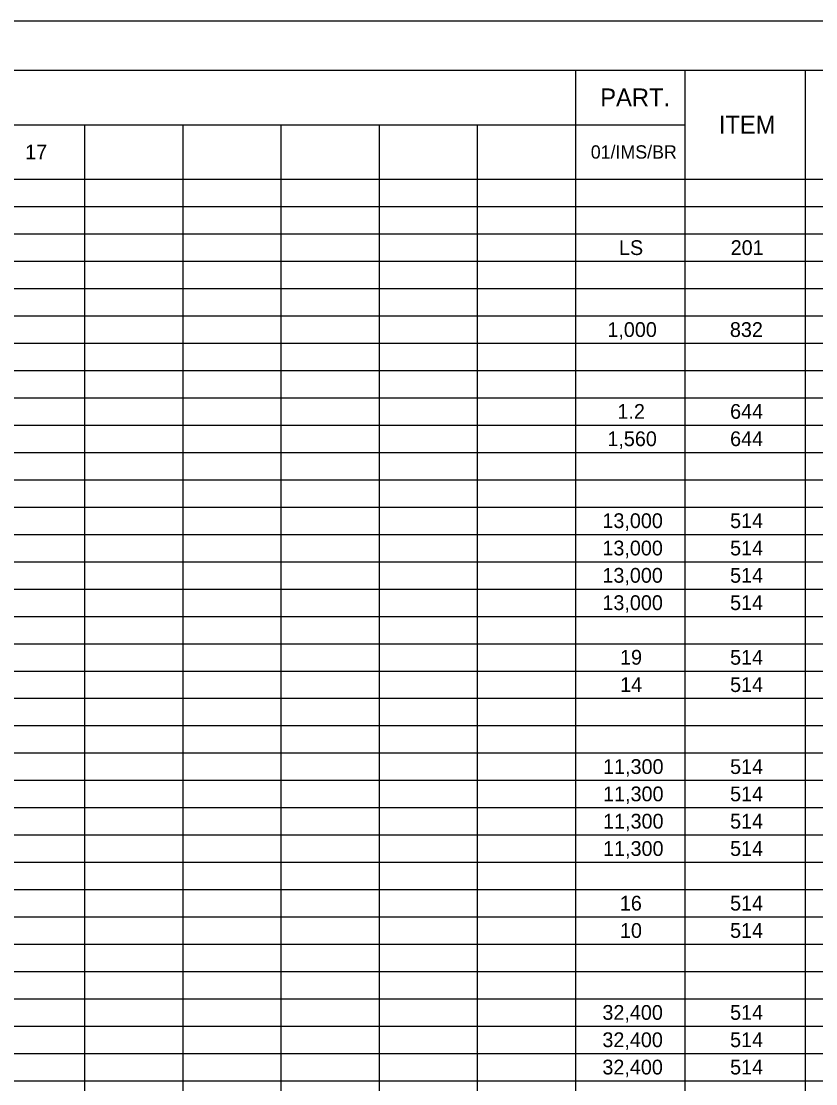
# Model space of a CAD drawing. Extents: x 0 to 34, y 0 to 22.
# Drawn here: x 8.9 to 17.04, y 11.11 to 22 of the extents above; entities that cross this region are included whole.
import ezdxf

# ---------------------------------------------------------------- set-up
doc = ezdxf.new("R2010")
doc.units = 0
for name, color, linetype in [('SH_Border', 7, 'Continuous'), ('SH_Cut_Line', 7, 'Continuous'), ('SH_Text', 7, 'Continuous')]:
    doc.layers.add(name, color=color, linetype=linetype)

msp = doc.modelspace()

# ---------------------------------------------------------------- linework, layer by layer
at = {"layer": 'SH_Border'}
msp.add_lwpolyline([(1.5, 21.5), (33.5, 21.5), (33.5, 0.5), (1.5, 0.5)], close=True, dxfattribs=at)
at = {"layer": 'SH_Cut_Line'}
msp.add_lwpolyline([(0, 0), (34, 0), (34, 22), (0, 22)], close=True, dxfattribs=at)
at = {"layer": 'SH_Text'}
for p, q in [((1.5, 21.5), (32, 21.5)), ((14.58, 21.5), (14.58, 0.502)), ((15.701, 21.5), (15.701, 0.502)), ((16.937, 21.5), (16.937, 0.502)), ((1.5, 20.94), (15.701, 20.94)), ((9.549, 20.94), (9.549, 0.502)), ((10.555, 20.94), (10.555, 0.502)), ((11.561, 20.94), (11.561, 0.502)), ((12.567, 20.94), (12.567, 0.502)), ((13.574, 20.94), (13.574, 0.502)), ((1.5, 20.38), (32, 20.38)), ((1.5, 20.1), (32, 20.1)), ((1.5, 19.82), (32, 19.82)), ((1.5, 19.54), (32, 19.54)), ((1.5, 19.26), (32, 19.26)), ((1.5, 18.98), (32, 18.98)), ((1.5, 18.7), (32, 18.7)), ((1.5, 18.42), (32, 18.42)), ((1.5, 18.14), (32, 18.14)), ((1.5, 17.86), (32, 17.86)), ((1.5, 17.58), (32, 17.58)), ((1.5, 17.3), (32, 17.3)), ((1.5, 17.02), (32, 17.02)), ((1.5, 16.74), (32, 16.74)), ((1.5, 16.46), (32, 16.46)), ((1.5, 16.18), (32, 16.18)), ((1.5, 15.9), (32, 15.9)), ((1.5, 15.62), (32, 15.62)), ((1.5, 15.34), (32, 15.34)), ((1.5, 15.061), (32, 15.061)), ((1.5, 14.781), (32, 14.781)), ((1.5, 14.501), (32, 14.501)), ((1.5, 14.221), (32, 14.221)), ((1.5, 13.941), (32, 13.941)), ((1.5, 13.661), (32, 13.661)), ((1.5, 13.381), (32, 13.381)), ((1.5, 13.101), (32, 13.101)), ((1.5, 12.821), (32, 12.821)), ((1.5, 12.541), (32, 12.541)), ((1.5, 12.261), (32, 12.261)), ((1.5, 11.981), (32, 11.981)), ((1.5, 11.701), (32, 11.701)), ((1.5, 11.421), (32, 11.421)), ((1.5, 11.141), (32, 11.141))]:
    msp.add_line(p, q, dxfattribs=at)

# ---------------------------------------------------------------- texts
for s, height, p in [('PART.', 0.1818, (14.835, 21.129)), ('ITEM', 0.1818, (16.05, 20.849)), ('17', 0.1515, (8.94, 20.584)), ('01/IMS/BR', 0.1364, (14.738, 20.592)), ('LS', 0.1515, (15.027, 19.604)), ('201', 0.1515, (16.172, 19.604)), ('1,000', 0.1515, (14.908, 18.764)), ('832', 0.1515, (16.164, 18.764)), ('1.2', 0.1515, (15.011, 17.925)), ('644', 0.1515, (16.166, 17.925)), ('1,560', 0.1515, (14.908, 17.645)), ('644', 0.1515, (16.166, 17.645)), ('13,000', 0.1515, (14.857, 16.805)), ('514', 0.1515, (16.166, 16.805)), ('13,000', 0.1515, (14.857, 16.525)), ('514', 0.1515, (16.166, 16.525)), ('13,000', 0.1515, (14.857, 16.245)), ('514', 0.1515, (16.166, 16.245)), ('13,000', 0.1515, (14.857, 15.965)), ('514', 0.1515, (16.166, 15.965)), ('19', 0.1515, (15.038, 15.405)), ('514', 0.1515, (16.166, 15.405)), ('14', 0.1515, (15.039, 15.125)), ('514', 0.1515, (16.166, 15.125)), ('11,300', 0.1515, (14.864, 14.285)), ('514', 0.1515, (16.166, 14.285)), ('11,300', 0.1515, (14.864, 14.005)), ('514', 0.1515, (16.166, 14.005)), ('11,300', 0.1515, (14.864, 13.725)), ('514', 0.1515, (16.166, 13.725)), ('11,300', 0.1515, (14.864, 13.445)), ('514', 0.1515, (16.166, 13.445)), ('16', 0.1515, (15.036, 12.885)), ('514', 0.1515, (16.166, 12.885)), ('10', 0.1515, (15.037, 12.605)), ('514', 0.1515, (16.166, 12.605)), ('32,400', 0.1515, (14.857, 11.765)), ('514', 0.1515, (16.166, 11.765)), ('32,400', 0.1515, (14.857, 11.485)), ('514', 0.1515, (16.166, 11.485)), ('32,400', 0.1515, (14.857, 11.205)), ('514', 0.1515, (16.166, 11.205))]:
    msp.add_text(s, height=height, dxfattribs=at).set_placement(p)

doc.saveas('drawing.dxf')
